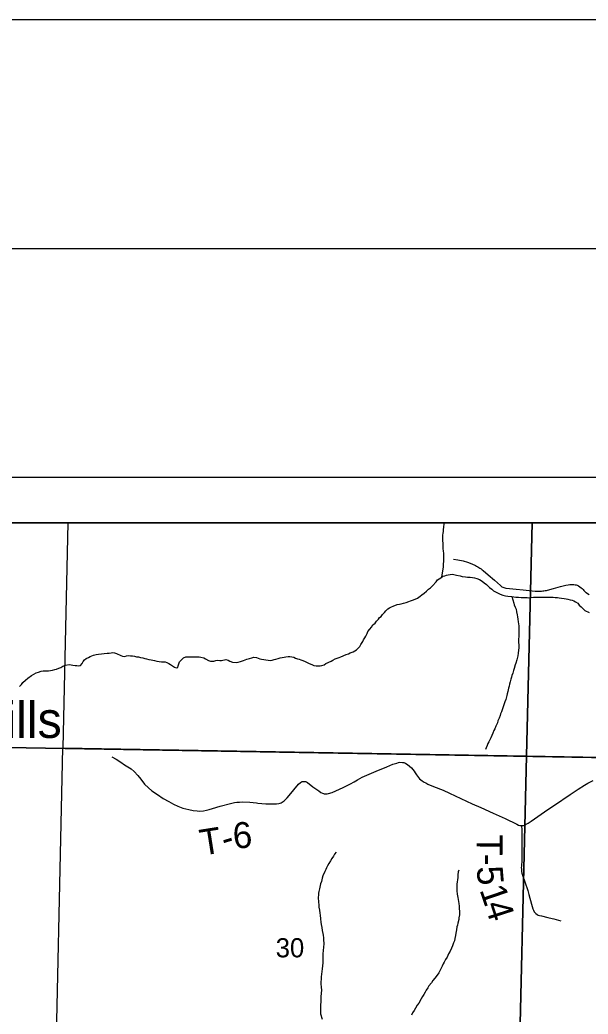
# Model space of a CAD drawing. Extents: x 0 to 34, y 0 to 22.
# Drawn here: x 27.832 to 29.074, y 19.826 to 22 of the extents above; entities that cross this region are included whole.
import ezdxf

# ---------------------------------------------------------------- set-up
doc = ezdxf.new("R2010")
doc.units = 0
for name, color, linetype in [('GM_X_Corporation', 7, 'Continuous'), ('GM_X_Minor_River', 7, 'Continuous'), ('GM_X_Section_Text', 7, 'Continuous'), ('GM_X_Township_Road', 7, 'Continuous'), ('GM_X_Township_Road_Text', 7, 'Continuous'), ('GM_X_Unincorporated_Text', 7, 'Continuous'), ('SH_Border', 7, 'Continuous'), ('SH_Cut_Line', 7, 'Continuous'), ('SH_Data', 7, 'Continuous')]:
    doc.layers.add(name, color=color, linetype=linetype)

msp = doc.modelspace()

# ---------------------------------------------------------------- linework, layer by layer
at = {"layer": 'GM_X_Corporation'}
for points in [[(30.3167, 20.3649), (30.3167, 20.9), (27.1022, 20.9), (27.0898, 20.417), (27.1239, 20.4163), (27.2336, 20.4152), (27.5829, 20.4116), (27.6751, 20.4106), (29.5503, 20.3788)], [(28.9521, 20.9), (27.9373, 20.9), (27.9263, 20.4078), (28.9396, 20.3907)], [(29.9786, 20.9), (28.9521, 20.9), (28.9396, 20.3907), (29.9657, 20.3723)], [(28.9396, 20.3907), (28.9198, 19.5578), (27.9077, 19.5783), (27.9263, 20.4078)], [(29.9657, 20.3723), (29.946, 19.5413), (28.9198, 19.5578), (28.9396, 20.3907)]]:
    msp.add_lwpolyline(points, close=True, dxfattribs=at)
for points in [[(27.8031, 14.5091), (28.4032, 14.497), (28.7853, 14.4893), (29.1713, 14.4832), (29.2367, 14.4822), (30.3098, 14.464), (30.3167, 14.4639), (30.3167, 20.9), (27.1022, 20.9)], [(27.8031, 14.5091), (28.4032, 14.497), (28.7853, 14.4893), (29.1713, 14.4832), (29.2367, 14.4822), (30.3098, 14.464), (30.3167, 14.4639), (30.3167, 20.3649), (29.5503, 20.3788), (27.6751, 20.4106)]]:
    msp.add_lwpolyline(points, dxfattribs=at)
at = {"layer": 'GM_X_Minor_River'}
for points in [[(28.7545, 20.7812), (28.7582, 20.8037), (28.7585, 20.8094), (28.7592, 20.8159), (28.7594, 20.822), (28.7593, 20.8276), (28.7589, 20.8329), (28.7584, 20.839), (28.7579, 20.8435), (28.7574, 20.85), (28.7573, 20.8557), (28.7569, 20.8606), (28.7567, 20.8727), (28.7573, 20.8773), (28.758, 20.8811), (28.7583, 20.8849), (28.759, 20.891), (28.7596, 20.8974), (28.7599, 20.9)], [(28.3751, 20.5994), (28.3792, 20.5991), (28.3838, 20.5996), (28.3879, 20.6008), (28.392, 20.602), (28.3966, 20.6032), (28.4011, 20.6048), (28.406, 20.6056), (28.4101, 20.6065), (28.4139, 20.6069), (28.4188, 20.6074), (28.4226, 20.6075), (28.4268, 20.6072), (28.431, 20.6061), (28.4348, 20.6043), (28.439, 20.6028), (28.4428, 20.6021), (28.4466, 20.6007), (28.4508, 20.5992), (28.4557, 20.597), (28.4649, 20.5927), (28.4706, 20.5901), (28.4752, 20.5883), (28.4797, 20.5872), (28.4843, 20.5869), (28.4888, 20.5874), (28.4926, 20.5882), (28.4975, 20.5898), (28.5012, 20.5922), (28.5125, 20.5977), (28.5162, 20.5996), (28.5218, 20.6024), (28.5256, 20.604), (28.5301, 20.6056), (28.5342, 20.6072), (28.5459, 20.6119), (28.5508, 20.6135), (28.5545, 20.6155), (28.5605, 20.6179), (28.5647, 20.6202), (28.5684, 20.6225), (28.5721, 20.626), (28.5755, 20.6299), (28.5777, 20.6341), (28.5817, 20.6402), (28.5835, 20.6444), (28.5861, 20.6483), (28.5883, 20.6521), (28.5913, 20.6582), (28.5927, 20.662), (28.5971, 20.6678), (28.6008, 20.672), (28.6038, 20.6766), (28.609, 20.6809), (28.6116, 20.6847), (28.6161, 20.689), (28.6187, 20.6928), (28.6224, 20.6955), (28.6253, 20.6994), (28.6294, 20.7036), (28.632, 20.7075), (28.6365, 20.7121), (28.6402, 20.7144), (28.6447, 20.7164), (28.6485, 20.718), (28.6568, 20.7212), (28.662, 20.722), (28.6658, 20.7228), (28.6711, 20.7241), (28.6767, 20.7257), (28.6827, 20.7281), (28.6865, 20.7293), (28.6906, 20.7309), (28.6963, 20.7332), (28.7012, 20.7356), (28.7075, 20.7399), (28.7113, 20.7426), (28.7161, 20.7465), (28.7209, 20.7507), (28.7254, 20.7546), (28.7299, 20.7581), (28.734, 20.762), (28.7422, 20.7712), (28.7451, 20.7751), (28.7489, 20.7778), (28.7526, 20.7797), (28.7571, 20.7832), (28.7609, 20.7844), (28.765, 20.7853), (28.7688, 20.7861), (28.7729, 20.7869), (28.7771, 20.7874), (28.7812, 20.7871), (28.7866, 20.7853), (28.7949, 20.7839), (28.7991, 20.7828), (28.8063, 20.7822), (28.8105, 20.7815), (28.8169, 20.7809), (28.8215, 20.7806), (28.8264, 20.7795)], [(28.8264, 20.7795), (28.831, 20.7781), (28.8367, 20.7759), (28.8428, 20.7722), (28.8474, 20.7689), (28.852, 20.7648), (28.8589, 20.7589), (28.8643, 20.7548), (28.8678, 20.7511), (28.8723, 20.7489), (28.8777, 20.7459), (28.8819, 20.7441), (28.888, 20.742), (28.8937, 20.7405), (28.899, 20.7395), (28.9077, 20.7389), (28.9119, 20.7382), (28.9164, 20.7375), (28.9221, 20.7372), (28.9282, 20.7366), (28.9327, 20.7367), (28.9373, 20.7364), (28.9411, 20.7364), (28.9452, 20.7361), (28.9498, 20.7366), (28.9554, 20.7371), (28.9603, 20.7372), (28.9641, 20.7376), (28.9694, 20.7373), (28.9751, 20.7374), (28.9789, 20.7371), (28.983, 20.7372), (28.9925, 20.7374), (28.9982, 20.7371), (29.0024, 20.7368), (29.0073, 20.7365), (29.0111, 20.7362), (29.0164, 20.7355), (29.0221, 20.7345), (29.0262, 20.7338), (29.03, 20.7331), (29.035, 20.7317), (29.0395, 20.7306), (29.0434, 20.7292), (29.0472, 20.7273), (29.0518, 20.724), (29.0549, 20.7199), (29.0591, 20.7162), (29.0637, 20.7117), (29.0676, 20.7084), (29.0767, 20.7036)], [(28.9076, 20.7389), (28.9118, 20.7242), (28.913, 20.7204), (28.9153, 20.7155), (28.9169, 20.7114), (28.9181, 20.7057), (28.9194, 20.6985), (28.9202, 20.6944), (28.9207, 20.6891), (28.9215, 20.6838), (28.9224, 20.6792), (28.9228, 20.6751), (28.9231, 20.658), (28.9229, 20.6519), (28.9226, 20.6451), (28.9229, 20.6265), (28.9226, 20.6216), (28.9216, 20.6151), (28.9206, 20.6091), (28.9188, 20.6007), (28.9163, 20.5931), (28.9152, 20.5892), (28.9131, 20.5812), (28.9113, 20.5767), (28.9099, 20.5713), (28.9077, 20.5663), (28.9066, 20.5622), (28.9056, 20.5583), (28.9042, 20.5526), (28.9027, 20.5473), (28.9017, 20.5427), (28.9002, 20.5382), (28.8992, 20.5313), (28.8974, 20.526), (28.8964, 20.5222), (28.8942, 20.5138), (28.8921, 20.5088), (28.891, 20.5042), (28.8892, 20.4997), (28.8863, 20.4913), (28.8852, 20.4867), (28.8831, 20.4825), (28.882, 20.4787), (28.8798, 20.4729), (28.8773, 20.4668), (28.8762, 20.4626), (28.8726, 20.455), (28.8704, 20.4496), (28.8686, 20.4458), (28.866, 20.4397), (28.8616, 20.4298), (28.8595, 20.4252), (28.8573, 20.4213), (28.8551, 20.4171), (28.8536, 20.4133), (28.8514, 20.408), (28.8504, 20.4042)], [(27.8949, 20.5766), (27.8994, 20.577), (27.9036, 20.5779), (27.9085, 20.5791), (27.9126, 20.5803), (27.9175, 20.5819), (27.922, 20.5839), (27.9261, 20.5862), (27.9317, 20.589), (27.9401, 20.5899), (27.9446, 20.5892), (27.9484, 20.5889), (27.9529, 20.5882), (27.9567, 20.5879), (27.9613, 20.5876), (27.9651, 20.5877), (27.9688, 20.5923), (27.9706, 20.5965), (27.9736, 20.6003), (27.9773, 20.6034), (27.9822, 20.6058), (27.9859, 20.6077), (27.9897, 20.6093), (27.9934, 20.6105), (27.9991, 20.6118), (28.0044, 20.613), (28.0233, 20.6148), (28.0274, 20.6149), (28.0316, 20.6158), (28.0353, 20.6162), (28.0395, 20.6159), (28.0437, 20.6144), (28.0528, 20.6101), (28.0567, 20.6086), (28.0616, 20.6079), (28.0654, 20.6088), (28.0699, 20.6096), (28.0744, 20.6093), (28.0782, 20.609), (28.0828, 20.6083), (28.087, 20.6072), (28.0915, 20.6066), (28.0957, 20.6055), (28.1014, 20.6045), (28.1056, 20.6034), (28.1094, 20.6027), (28.1139, 20.6013), (28.1192, 20.6002), (28.1265, 20.5988), (28.1314, 20.5978), (28.1416, 20.5961), (28.1454, 20.5958), (28.15, 20.5958), (28.1538, 20.5948), (28.158, 20.5926), (28.1618, 20.59), (28.1656, 20.587), (28.1702, 20.5841), (28.174, 20.5826), (28.1778, 20.5834), (28.1785, 20.5876), (28.1799, 20.5914), (28.1814, 20.596), (28.1862, 20.6014), (28.1903, 20.6049), (28.1952, 20.6069), (28.1993, 20.6073), (28.2031, 20.607), (28.2168, 20.6072), (28.2205, 20.6069), (28.2243, 20.607), (28.2281, 20.6063), (28.2342, 20.6045), (28.2384, 20.6027), (28.2445, 20.599), (28.2487, 20.5972), (28.2525, 20.5973), (28.2563, 20.5977), (28.2608, 20.5989), (28.2653, 20.5994), (28.2695, 20.5987), (28.2733, 20.5988), (28.2823, 20.6012), (28.2873, 20.5998), (28.2915, 20.5972), (28.2968, 20.5954), (28.3059, 20.5948), (28.3097, 20.5956), (28.3149, 20.5968), (28.321, 20.5988), (28.3281, 20.6016), (28.3345, 20.6036), (28.339, 20.6048), (28.3439, 20.6061), (28.3492, 20.6054), (28.353, 20.6043), (28.3568, 20.6029), (28.3606, 20.6022), (28.3656, 20.6011), (28.3698, 20.6001), (28.3751, 20.5994)], [(27.8312, 20.5417), (27.8356, 20.5463), (27.8386, 20.5506), (27.8445, 20.556), (27.8494, 20.5602), (27.858, 20.5664), (27.8625, 20.5688), (27.8681, 20.5719), (27.873, 20.5735), (27.8786, 20.5755), (27.8832, 20.5764), (27.8949, 20.5766)], [(28.5239, 20.1795), (28.5198, 20.1757), (28.5177, 20.1711), (28.5143, 20.1661), (28.5114, 20.1611), (28.5077, 20.155), (28.5048, 20.1496), (28.5026, 20.1458), (28.5008, 20.1416), (28.4986, 20.1374), (28.4949, 20.1282), (28.4931, 20.1229), (28.4918, 20.1156), (28.4896, 20.1107), (28.4885, 20.1065), (28.4875, 20.0996), (28.4861, 20.0939), (28.4854, 20.0901), (28.4851, 20.0855), (28.4844, 20.0814), (28.4854, 20.0696), (28.4855, 20.0655), (28.4859, 20.0598), (28.4872, 20.053), (28.4877, 20.0461), (28.4885, 20.042), (28.4894, 20.0337), (28.4903, 20.0268), (28.4912, 20.0212), (28.492, 20.0151), (28.4933, 20.0087), (28.4949, 20.0019), (28.495, 19.9981), (28.4958, 19.9924), (28.4963, 19.9875), (28.4964, 19.9807), (28.4958, 19.9708), (28.4952, 19.9659), (28.4946, 19.9556), (28.4947, 19.9507), (28.4947, 19.9461), (28.4949, 19.9378), (28.4939, 19.9313), (28.4932, 19.9248), (28.4915, 19.9127), (28.4909, 19.9074), (28.4906, 19.902), (28.4903, 19.896), (28.4904, 19.8918), (28.4909, 19.8846), (28.4914, 19.8782), (28.4901, 19.8641), (28.4902, 19.8603), (28.4899, 19.8561), (28.49, 19.8519), (28.4897, 19.8466), (28.4894, 19.8421), (28.4891, 19.8349), (28.4892, 19.8311), (28.4897, 19.8261), (28.4929, 19.8148)], [(28.7918, 20.1403), (28.7907, 20.1365), (28.7897, 20.13), (28.7894, 20.1239), (28.7887, 20.1201), (28.7881, 20.114), (28.7878, 20.1102), (28.7871, 20.1034), (28.7873, 20.0954), (28.7882, 20.0882), (28.7894, 20.0803), (28.7903, 20.0765), (28.7916, 20.0671), (28.7924, 20.0618), (28.7929, 20.0549), (28.7934, 20.0512), (28.7934, 20.0462), (28.7931, 20.0424), (28.7921, 20.036), (28.7918, 20.0322), (28.7897, 20.0242), (28.7886, 20.0203), (28.7875, 20.0162), (28.7865, 20.0097), (28.7855, 20.0028), (28.7845, 19.9975), (28.7831, 19.9907), (28.782, 19.9861), (28.7802, 19.9811), (28.7777, 19.9746), (28.7755, 19.97), (28.7726, 19.9632), (28.7693, 19.9574), (28.766, 19.9498), (28.7627, 19.9448), (28.7601, 19.939), (28.7576, 19.9352), (28.7557, 19.9306), (28.751, 19.9214), (28.7481, 19.9161), (28.7447, 19.9107), (28.7392, 19.9045), (28.7347, 19.8991), (28.7318, 19.8938), (28.7266, 19.8872), (28.7237, 19.883), (28.7207, 19.8776), (28.7181, 19.8738), (28.7156, 19.8685), (28.7123, 19.8638), (28.7097, 19.8589), (28.7042, 19.8497), (28.7009, 19.8451), (28.6972, 19.8389), (28.6943, 19.8336), (28.6909, 19.8282), (28.688, 19.8236)]]:
    msp.add_lwpolyline(points, dxfattribs=at)
at = {"layer": 'GM_X_Township_Road'}
for points in [[(28.7799, 20.8207), (28.7895, 20.8191), (28.8016, 20.8166), (28.8108, 20.8139), (28.8203, 20.8103), (28.8229, 20.8092), (28.8255, 20.8079), (28.828, 20.8067), (28.8306, 20.8053), (28.833, 20.8039), (28.8355, 20.8024), (28.8379, 20.8008), (28.8403, 20.7992), (28.8426, 20.7975), (28.8449, 20.7958), (28.8563, 20.7862), (28.8701, 20.7747), (28.8832, 20.7627), (28.885, 20.7611), (28.8859, 20.7604), (28.8879, 20.7592), (28.89, 20.7583), (28.8923, 20.7576), (28.8946, 20.7572), (28.9023, 20.7565), (28.9171, 20.755), (28.9322, 20.7535), (28.9455, 20.7522), (28.9589, 20.7509), (28.9643, 20.7507), (28.9697, 20.7508), (28.9724, 20.7509), (28.9751, 20.7512), (28.9778, 20.7515), (28.9805, 20.7519), (28.9831, 20.7523), (28.9858, 20.7529), (28.9884, 20.7535), (28.991, 20.7542), (28.9936, 20.7549), (28.9961, 20.7558), (28.9987, 20.7566), (29.0138, 20.7607), (29.0257, 20.7635), (29.0309, 20.7645), (29.0341, 20.765), (29.0369, 20.7651), (29.0431, 20.765), (29.0458, 20.7647), (29.0481, 20.7643), (29.0503, 20.7636), (29.0532, 20.762), (29.0591, 20.758), (29.0615, 20.7561), (29.0636, 20.7543), (29.0654, 20.7523), (29.0674, 20.75), (29.0688, 20.7487), (29.0703, 20.7475), (29.0733, 20.7452), (29.0764, 20.7432)], [(28.0335, 20.3879), (28.0427, 20.3834), (28.0533, 20.3763), (28.0612, 20.3708), (28.0683, 20.3663), (28.0756, 20.3617), (28.0823, 20.3564), (28.09, 20.3477), (28.0967, 20.3392), (28.105, 20.3288), (28.1137, 20.3201), (28.1211, 20.3139), (28.1329, 20.306), (28.1458, 20.2974), (28.1577, 20.2906), (28.1682, 20.2847), (28.1777, 20.2802), (28.1887, 20.2761), (28.2013, 20.273), (28.2112, 20.271), (28.2196, 20.2699), (28.226, 20.2695), (28.2338, 20.2703), (28.2402, 20.2716), (28.2462, 20.2732), (28.2534, 20.2752), (28.2703, 20.28), (28.2929, 20.2865), (28.2959, 20.2872), (28.3014, 20.2882), (28.3069, 20.2889), (28.3124, 20.2893), (28.3189, 20.2895), (28.3347, 20.2888), (28.3495, 20.2874), (28.3521, 20.2872), (28.3698, 20.2857), (28.3827, 20.2853), (28.3936, 20.2855), (28.3984, 20.2861), (28.4011, 20.2869), (28.4036, 20.2879), (28.4076, 20.2903), (28.4101, 20.2923), (28.4132, 20.295), (28.4165, 20.2986), (28.4206, 20.3036), (28.4416, 20.3284), (28.4459, 20.3323), (28.4476, 20.3333), (28.4494, 20.334), (28.4513, 20.3344), (28.4532, 20.3346), (28.4551, 20.3344), (28.457, 20.334), (28.459, 20.3332), (28.4607, 20.3321), (28.473, 20.3228), (28.4857, 20.3136), (28.4904, 20.3105), (28.4935, 20.3089), (28.4958, 20.308), (28.4978, 20.3075), (28.4994, 20.3073), (28.5018, 20.3071), (28.5042, 20.3073), (28.5067, 20.3077), (28.5147, 20.3101), (28.5393, 20.3214), (28.5494, 20.3262), (28.555, 20.3291), (28.5633, 20.3337), (28.5706, 20.3382), (28.5754, 20.341), (28.5804, 20.3436), (28.5855, 20.346), (28.5906, 20.3482), (28.6109, 20.3566), (28.6343, 20.3667), (28.6476, 20.3719), (28.6561, 20.3747), (28.6602, 20.3759), (28.6632, 20.3764), (28.6687, 20.3762), (28.6714, 20.3757), (28.6739, 20.3749), (28.676, 20.3739), (28.6795, 20.3714), (28.688, 20.364), (28.6912, 20.3604), (28.6941, 20.3566), (28.6965, 20.3532), (28.6995, 20.3487), (28.7016, 20.3457), (28.7039, 20.3428), (28.706, 20.3404), (28.7084, 20.3381), (28.7119, 20.3355), (28.7157, 20.3331), (28.7194, 20.3311), (28.7243, 20.3288), (28.7368, 20.3237), (28.7578, 20.315), (28.7717, 20.3086), (28.8209, 20.2857), (28.8397, 20.2772), (28.8668, 20.265), (28.893, 20.2531), (28.9183, 20.2409), (28.9223, 20.2391), (28.9253, 20.2381), (28.9272, 20.2378), (28.9288, 20.2378), (28.9303, 20.2378), (28.9329, 20.2382), (28.9357, 20.239), (28.9377, 20.2399), (28.9408, 20.2416), (28.9434, 20.2434), (28.9497, 20.2477), (28.9861, 20.2727), (29.0008, 20.2824), (29.0352, 20.3055), (29.053, 20.3173), (29.0665, 20.3261), (29.0741, 20.3308), (29.0854, 20.3364)], [(28.9288, 20.2378), (28.9294, 20.2275), (28.9297, 20.2134), (28.9296, 20.1803), (28.9293, 20.1624), (28.9286, 20.1492), (28.9284, 20.1461), (28.9285, 20.1426), (28.9291, 20.1376), (28.9298, 20.1339), (28.9309, 20.1294), (28.936, 20.1145), (28.9423, 20.0961), (28.9447, 20.0873), (28.9505, 20.066), (28.9537, 20.0559), (28.9551, 20.0526), (28.9567, 20.0496), (28.9584, 20.0473), (28.9604, 20.0453), (28.9629, 20.0437), (28.9655, 20.0423), (28.9684, 20.0413), (28.9724, 20.0403), (28.9867, 20.0368), (28.9896, 20.036)], [(28.9896, 20.036), (28.9993, 20.0336), (29.0149, 20.0293)]]:
    msp.add_lwpolyline(points, dxfattribs=at)
at = {"layer": 'SH_Border'}
msp.add_lwpolyline([(1.5, 21.5), (33.5, 21.5), (33.5, 0.5), (1.5, 0.5)], close=True, dxfattribs=at)
at = {"layer": 'SH_Cut_Line'}
msp.add_lwpolyline([(0, 0), (34, 0), (34, 22), (0, 22)], close=True, dxfattribs=at)
at = {"layer": 'SH_Data'}
for points in [[(23.4167, 21), (30.4167, 21), (30.4167, 14), (23.4167, 14)], [(23.5167, 20.9), (30.3167, 20.9), (30.3167, 14.1), (23.5167, 14.1)]]:
    msp.add_lwpolyline(points, close=True, dxfattribs=at)

# ---------------------------------------------------------------- texts
at = {"layer": 'GM_X_Section_Text'}
msp.add_text('30', height=0.04186, rotation=0, dxfattribs=at).set_placement((28.3916, 19.9497))
at = {"layer": 'GM_X_Township_Road_Text'}
for s, rotation, p in [('6', 4.6573, (28.2999, 20.187)), ('T', 8.9762, (28.2302, 20.172)), ('-', 17.2386, (28.2809, 20.1807)), ('T', 269.4472, (28.8309, 20.2189)), ('-', 269.8376, (28.8305, 20.176)), ('5', 274.5439, (28.8306, 20.1476)), ('1', 288.909, (28.8366, 20.0976)), ('4', 287.8228, (28.8478, 20.0647))]:
    msp.add_text(s, height=0.0568, rotation=rotation, dxfattribs=at).set_placement(p)
at = {"layer": 'GM_X_Unincorporated_Text'}
msp.add_text('Baileys Mills', height=0.078977, rotation=0, dxfattribs=at).set_placement((27.3429, 20.4296))

doc.saveas('drawing.dxf')
